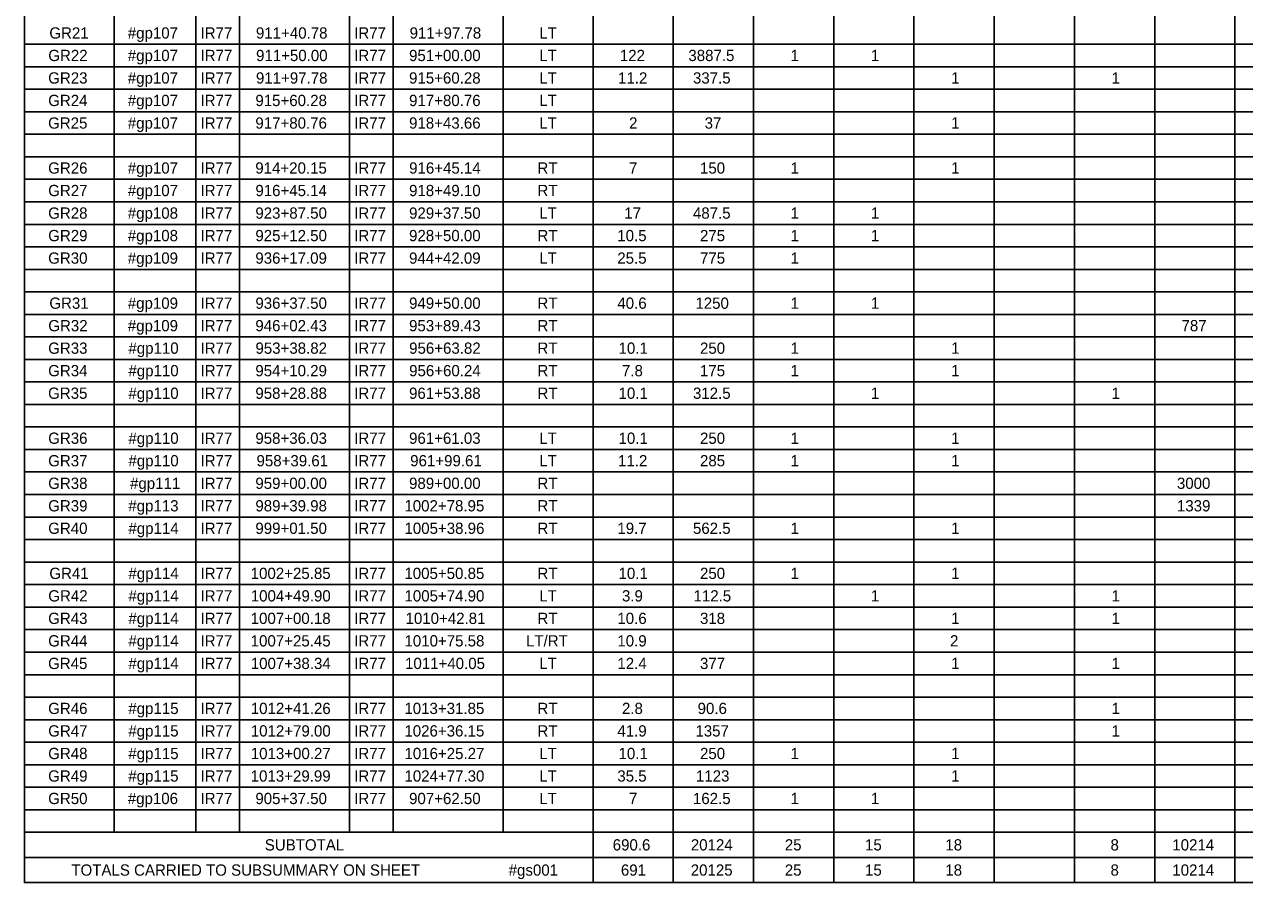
# Model space of a CAD drawing. Extents: x -542 to 295, y -281 to 32.
# Drawn here: x -16.42 to -1.5, y -100.59 to -90.1 of the extents above; entities that cross this region are included whole.
import ezdxf

# ---------------------------------------------------------------- set-up
doc = ezdxf.new("R2010")
doc.units = 0
doc.layers.add('SC_Scratch1', color=7, linetype='Continuous')
doc.layers.add('SH_Text', color=7, linetype='Continuous')

msp = doc.modelspace()

# ---------------------------------------------------------------- linework, layer by layer
at = {"layer": 'SC_Scratch1'}
msp.add_lwpolyline([(-16.421, -79.593), (14.079, -79.593), (14.079, -100.593), (-16.421, -100.593)], close=True, dxfattribs=at)
at = {"layer": 'SH_Text'}
for p, q in [((-16.421, -79.593), (-16.421, -100.593)), ((-15.323, -79.593), (-15.323, -99.977)), ((-14.325, -79.593), (-14.325, -99.977)), ((-10.567, -79.593), (-10.567, -99.977)), ((-9.469, -79.593), (-9.469, -100.593)), ((-8.488, -79.593), (-8.488, -100.593)), ((-7.507, -79.593), (-7.507, -100.593)), ((-6.526, -79.593), (-6.526, -100.593)), ((-5.545, -79.593), (-5.545, -100.593)), ((-4.563, -79.593), (-4.563, -100.593)), ((-3.582, -79.593), (-3.582, -100.593)), ((-2.601, -79.593), (-2.601, -100.593)), ((-1.62, -79.593), (-1.62, -100.593)), ((-12.446, -82.847), (-12.446, -99.977)), ((-13.793, -83.187), (-13.793, -99.977)), ((-11.914, -83.187), (-11.914, -99.977)), ((-16.421, -90.344), (14.079, -90.344)), ((-16.421, -90.619), (14.079, -90.619)), ((-16.421, -90.894), (14.079, -90.894)), ((-16.421, -91.169), (14.079, -91.169)), ((-16.421, -91.445), (14.079, -91.445)), ((-16.421, -91.72), (14.079, -91.72)), ((-16.421, -91.995), (14.079, -91.995)), ((-16.421, -92.27), (14.079, -92.27)), ((-16.421, -92.546), (14.079, -92.546)), ((-16.421, -92.821), (14.079, -92.821)), ((-16.421, -93.096), (14.079, -93.096)), ((-16.421, -93.371), (14.079, -93.371)), ((-16.421, -93.647), (14.079, -93.647)), ((-16.421, -93.922), (14.079, -93.922)), ((-16.421, -94.197), (14.079, -94.197)), ((-16.421, -94.472), (14.079, -94.472)), ((-16.421, -94.748), (14.079, -94.748)), ((-16.421, -95.023), (14.079, -95.023)), ((-16.421, -95.298), (14.079, -95.298)), ((-16.421, -95.573), (14.079, -95.573)), ((-16.421, -95.849), (14.079, -95.849)), ((-16.421, -96.124), (14.079, -96.124)), ((-16.421, -96.399), (14.079, -96.399)), ((-16.421, -96.674), (14.079, -96.674)), ((-16.421, -96.95), (14.079, -96.95)), ((-16.421, -97.225), (14.079, -97.225)), ((-16.421, -97.5), (14.079, -97.5)), ((-16.421, -97.775), (14.079, -97.775)), ((-16.421, -98.051), (14.079, -98.051)), ((-16.421, -98.326), (14.079, -98.326)), ((-16.421, -98.601), (14.079, -98.601)), ((-16.421, -98.876), (14.079, -98.876)), ((-16.421, -99.152), (14.079, -99.152)), ((-16.421, -99.427), (14.079, -99.427)), ((-16.421, -99.702), (14.079, -99.702)), ((-16.421, -99.977), (14.079, -99.977)), ((-16.421, -100.285), (14.079, -100.285)), ((-16.421, -100.593), (14.079, -100.593))]:
    msp.add_line(p, q, dxfattribs=at)

# ---------------------------------------------------------------- texts
for s, height, p in [('GR21', 0.1376, (-16.116, -90.275)), ('#gp107', 0.1376, (-15.157, -90.275)), ('IR77', 0.1376, (-14.268, -90.275)), ('911+40.78', 0.1376, (-13.59, -90.275)), ('IR77', 0.1376, (-12.389, -90.275)), ('911+97.78', 0.1376, (-11.711, -90.275)), ('LT', 0.1376, (-10.126, -90.275)), ('GR22', 0.1376, (-16.129, -90.55)), ('#gp107', 0.1376, (-15.157, -90.55)), ('IR77', 0.1376, (-14.268, -90.55)), ('911+50.00', 0.1376, (-13.589, -90.55)), ('IR77', 0.1376, (-12.389, -90.55)), ('951+00.00', 0.1376, (-11.718, -90.55)), ('LT', 0.1376, (-10.126, -90.55)), ('122', 0.1376, (-9.141, -90.55)), ('3887.5', 0.1376, (-8.303, -90.55)), ('1', 0.138, (-7.053, -90.55)), ('1', 0.138, (-6.072, -90.55)), ('GR23', 0.1376, (-16.13, -90.825)), ('#gp107', 0.1376, (-15.157, -90.825)), ('IR77', 0.1376, (-14.268, -90.825)), ('911+97.78', 0.1376, (-13.59, -90.825)), ('IR77', 0.1376, (-12.389, -90.825)), ('915+60.28', 0.1376, (-11.718, -90.825)), ('LT', 0.1376, (-10.126, -90.825)), ('11.2', 0.1376, (-9.163, -90.825)), ('337.5', 0.1376, (-8.247, -90.825)), ('1', 0.138, (-5.091, -90.825)), ('1', 0.138, (-3.128, -90.825)), ('GR24', 0.1376, (-16.13, -91.1)), ('#gp107', 0.1376, (-15.157, -91.1)), ('IR77', 0.1376, (-14.268, -91.1)), ('915+60.28', 0.1376, (-13.597, -91.1)), ('IR77', 0.1376, (-12.389, -91.1)), ('917+80.76', 0.1376, (-11.718, -91.1)), ('LT', 0.1376, (-10.126, -91.1)), ('GR25', 0.1376, (-16.131, -91.376)), ('#gp107', 0.1376, (-15.157, -91.376)), ('IR77', 0.1376, (-14.268, -91.376)), ('917+80.76', 0.1376, (-13.597, -91.376)), ('IR77', 0.1376, (-12.389, -91.376)), ('918+43.66', 0.1376, (-11.718, -91.376)), ('LT', 0.1376, (-10.126, -91.376)), ('2', 0.138, (-9.028, -91.376)), ('37', 0.1376, (-8.104, -91.376)), ('1', 0.138, (-5.091, -91.376)), ('GR26', 0.1376, (-16.13, -91.926)), ('#gp107', 0.1376, (-15.157, -91.926)), ('IR77', 0.1376, (-14.268, -91.926)), ('914+20.15', 0.1376, (-13.598, -91.926)), ('IR77', 0.1376, (-12.389, -91.926)), ('916+45.14', 0.1376, (-11.717, -91.926)), ('RT', 0.1376, (-10.148, -91.926)), ('7', 0.138, (-9.029, -91.926)), ('150', 0.1376, (-8.161, -91.926)), ('1', 0.138, (-7.053, -91.926)), ('1', 0.138, (-5.091, -91.926)), ('GR27', 0.1376, (-16.13, -92.201)), ('#gp107', 0.1376, (-15.157, -92.201)), ('IR77', 0.1376, (-14.268, -92.201)), ('916+45.14', 0.1376, (-13.597, -92.201)), ('IR77', 0.1376, (-12.389, -92.201)), ('918+49.10', 0.1376, (-11.718, -92.201)), ('RT', 0.1376, (-10.148, -92.201)), ('GR28', 0.1376, (-16.13, -92.477)), ('#gp108', 0.1376, (-15.157, -92.477)), ('IR77', 0.1376, (-14.268, -92.477)), ('923+87.50', 0.1376, (-13.597, -92.477)), ('IR77', 0.1376, (-12.389, -92.477)), ('929+37.50', 0.1376, (-11.718, -92.477)), ('LT', 0.1376, (-10.126, -92.477)), ('17', 0.1376, (-9.086, -92.477)), ('487.5', 0.1376, (-8.247, -92.477)), ('1', 0.138, (-7.053, -92.477)), ('1', 0.138, (-6.072, -92.477)), ('GR29', 0.1376, (-16.13, -92.752)), ('#gp108', 0.1376, (-15.157, -92.752)), ('IR77', 0.1376, (-14.268, -92.752)), ('925+12.50', 0.1376, (-13.597, -92.752)), ('IR77', 0.1376, (-12.389, -92.752)), ('928+50.00', 0.1376, (-11.718, -92.752)), ('RT', 0.1376, (-10.148, -92.752)), ('10.5', 0.1376, (-9.172, -92.752)), ('275', 0.1376, (-8.161, -92.752)), ('1', 0.138, (-7.053, -92.752)), ('1', 0.138, (-6.072, -92.752)), ('GR30', 0.1376, (-16.13, -93.027)), ('#gp109', 0.1376, (-15.157, -93.027)), ('IR77', 0.1376, (-14.268, -93.027)), ('936+17.09', 0.1376, (-13.597, -93.027)), ('IR77', 0.1376, (-12.389, -93.027)), ('944+42.09', 0.1376, (-11.718, -93.027)), ('LT', 0.1376, (-10.126, -93.027)), ('25.5', 0.1376, (-9.172, -93.027)), ('775', 0.1376, (-8.161, -93.027)), ('1', 0.138, (-7.053, -93.027)), ('GR31', 0.1376, (-16.116, -93.578)), ('#gp109', 0.1376, (-15.157, -93.578)), ('IR77', 0.1376, (-14.268, -93.578)), ('936+37.50', 0.1376, (-13.597, -93.578)), ('IR77', 0.1376, (-12.389, -93.578)), ('949+50.00', 0.1376, (-11.718, -93.578)), ('RT', 0.1376, (-10.148, -93.578)), ('40.6', 0.1376, (-9.171, -93.578)), ('1250', 0.1376, (-8.217, -93.578)), ('1', 0.138, (-7.053, -93.578)), ('1', 0.138, (-6.072, -93.578)), ('GR32', 0.1376, (-16.129, -93.853)), ('#gp109', 0.1376, (-15.157, -93.853)), ('IR77', 0.1376, (-14.268, -93.853)), ('946+02.43', 0.1376, (-13.597, -93.853)), ('IR77', 0.1376, (-12.389, -93.853)), ('953+89.43', 0.1376, (-11.718, -93.853)), ('RT', 0.1376, (-10.148, -93.853)), ('787', 0.1376, (-2.274, -93.853)), ('GR33', 0.1376, (-16.13, -94.128)), ('#gp110', 0.1376, (-15.149, -94.128)), ('IR77', 0.1376, (-14.268, -94.128)), ('953+38.82', 0.1376, (-13.596, -94.128)), ('IR77', 0.1376, (-12.389, -94.128)), ('956+63.82', 0.1376, (-11.717, -94.128)), ('RT', 0.1376, (-10.148, -94.128)), ('10.1', 0.1376, (-9.157, -94.128)), ('250', 0.1376, (-8.161, -94.128)), ('1', 0.138, (-7.053, -94.128)), ('1', 0.138, (-5.091, -94.128)), ('GR34', 0.1376, (-16.13, -94.403)), ('#gp110', 0.1376, (-15.149, -94.403)), ('IR77', 0.1376, (-14.268, -94.403)), ('954+10.29', 0.1376, (-13.597, -94.403)), ('IR77', 0.1376, (-12.389, -94.403)), ('956+60.24', 0.1376, (-11.717, -94.403)), ('RT', 0.1376, (-10.148, -94.403)), ('7.8', 0.1376, (-9.115, -94.403)), ('175', 0.1376, (-8.161, -94.403)), ('1', 0.138, (-7.053, -94.403)), ('1', 0.138, (-5.091, -94.403)), ('GR35', 0.1376, (-16.131, -94.679)), ('#gp110', 0.1376, (-15.149, -94.679)), ('IR77', 0.1376, (-14.268, -94.679)), ('958+28.88', 0.1376, (-13.597, -94.679)), ('IR77', 0.1376, (-12.389, -94.679)), ('961+53.88', 0.1376, (-11.718, -94.679)), ('RT', 0.1376, (-10.148, -94.679)), ('10.1', 0.1376, (-9.157, -94.679)), ('312.5', 0.1376, (-8.247, -94.679)), ('1', 0.138, (-6.072, -94.679)), ('1', 0.138, (-3.128, -94.679)), ('GR36', 0.1376, (-16.13, -95.229)), ('#gp110', 0.1376, (-15.149, -95.229)), ('IR77', 0.1376, (-14.268, -95.229)), ('958+36.03', 0.1376, (-13.597, -95.229)), ('IR77', 0.1376, (-12.389, -95.229)), ('961+61.03', 0.1376, (-11.718, -95.229)), ('LT', 0.1376, (-10.126, -95.229)), ('10.1', 0.1376, (-9.157, -95.229)), ('250', 0.1376, (-8.161, -95.229)), ('1', 0.138, (-7.053, -95.229)), ('1', 0.138, (-5.091, -95.229)), ('GR37', 0.1376, (-16.13, -95.504)), ('#gp110', 0.1376, (-15.149, -95.504)), ('IR77', 0.1376, (-14.268, -95.504)), ('958+39.61', 0.1376, (-13.583, -95.504)), ('IR77', 0.1376, (-12.389, -95.504)), ('961+99.61', 0.1376, (-11.704, -95.504)), ('LT', 0.1376, (-10.126, -95.504)), ('11.2', 0.1376, (-9.163, -95.504)), ('285', 0.1376, (-8.161, -95.504)), ('1', 0.138, (-7.053, -95.504)), ('1', 0.138, (-5.091, -95.504)), ('GR38', 0.1376, (-16.13, -95.78)), ('#gp111', 0.1376, (-15.129, -95.78)), ('IR77', 0.1376, (-14.268, -95.78)), ('959+00.00', 0.1376, (-13.597, -95.78)), ('IR77', 0.1376, (-12.389, -95.78)), ('989+00.00', 0.1376, (-11.718, -95.78)), ('RT', 0.1376, (-10.148, -95.78)), ('3000', 0.1376, (-2.33, -95.78)), ('GR39', 0.1376, (-16.13, -96.055)), ('#gp113', 0.1376, (-15.15, -96.055)), ('IR77', 0.1376, (-14.268, -96.055)), ('989+39.98', 0.1376, (-13.597, -96.055)), ('IR77', 0.1376, (-12.389, -96.055)), ('1002+78.95', 0.1376, (-11.775, -96.055)), ('RT', 0.1376, (-10.148, -96.055)), ('1339', 0.1376, (-2.33, -96.055)), ('GR40', 0.1376, (-16.13, -96.33)), ('#gp114', 0.1376, (-15.149, -96.33)), ('IR77', 0.1376, (-14.268, -96.33)), ('999+01.50', 0.1376, (-13.597, -96.33)), ('IR77', 0.1376, (-12.389, -96.33)), ('1005+38.96', 0.1376, (-11.774, -96.33)), ('RT', 0.1376, (-10.148, -96.33)), ('19.7', 0.1376, (-9.171, -96.33)), ('562.5', 0.1376, (-8.247, -96.33)), ('1', 0.138, (-7.053, -96.33)), ('1', 0.138, (-5.091, -96.33)), ('GR41', 0.1376, (-16.116, -96.881)), ('#gp114', 0.1376, (-15.149, -96.881)), ('IR77', 0.1376, (-14.268, -96.881)), ('1002+25.85', 0.1376, (-13.654, -96.881)), ('IR77', 0.1376, (-12.389, -96.881)), ('1005+50.85', 0.1376, (-11.775, -96.881)), ('RT', 0.1376, (-10.148, -96.881)), ('10.1', 0.1376, (-9.157, -96.881)), ('250', 0.1376, (-8.161, -96.881)), ('1', 0.138, (-7.053, -96.881)), ('1', 0.138, (-5.091, -96.881)), ('GR42', 0.1376, (-16.129, -97.156)), ('#gp114', 0.1376, (-15.149, -97.156)), ('IR77', 0.1376, (-14.268, -97.156)), ('1004+49.90', 0.1376, (-13.653, -97.156)), ('IR77', 0.1376, (-12.389, -97.156)), ('1005+74.90', 0.1376, (-11.774, -97.156)), ('LT', 0.1376, (-10.126, -97.156)), ('3.9', 0.1376, (-9.115, -97.156)), ('112.5', 0.1376, (-8.24, -97.156)), ('1', 0.138, (-6.072, -97.156)), ('1', 0.138, (-3.128, -97.156)), ('GR43', 0.1376, (-16.13, -97.431)), ('#gp114', 0.1376, (-15.149, -97.431)), ('IR77', 0.1376, (-14.268, -97.431)), ('1007+00.18', 0.1376, (-13.654, -97.431)), ('IR77', 0.1376, (-12.389, -97.431)), ('1010+42.81', 0.1376, (-11.761, -97.431)), ('RT', 0.1376, (-10.148, -97.431)), ('10.6', 0.1376, (-9.171, -97.431)), ('318', 0.1376, (-8.161, -97.431)), ('1', 0.138, (-5.091, -97.431)), ('1', 0.138, (-3.128, -97.431)), ('LT/RT', 0.1376, (-10.288, -97.706)), ('GR44', 0.1376, (-16.13, -97.706)), ('#gp114', 0.1376, (-15.149, -97.706)), ('IR77', 0.1376, (-14.268, -97.706)), ('1007+25.45', 0.1376, (-13.654, -97.706)), ('IR77', 0.1376, (-12.389, -97.706)), ('1010+75.58', 0.1376, (-11.774, -97.706)), ('10.9', 0.1376, (-9.171, -97.706)), ('2', 0.138, (-5.104, -97.706)), ('GR45', 0.1376, (-16.131, -97.982)), ('#gp114', 0.1376, (-15.149, -97.982)), ('IR77', 0.1376, (-14.268, -97.982)), ('1007+38.34', 0.1376, (-13.653, -97.982)), ('IR77', 0.1376, (-12.389, -97.982)), ('1011+40.05', 0.1376, (-11.767, -97.982)), ('LT', 0.1376, (-10.126, -97.982)), ('12.4', 0.1376, (-9.171, -97.982)), ('377', 0.1376, (-8.161, -97.982)), ('1', 0.138, (-5.091, -97.982)), ('1', 0.138, (-3.128, -97.982)), ('GR46', 0.1376, (-16.13, -98.532)), ('#gp115', 0.1376, (-15.15, -98.532)), ('IR77', 0.1376, (-14.268, -98.532)), ('1012+41.26', 0.1376, (-13.653, -98.532)), ('IR77', 0.1376, (-12.389, -98.532)), ('1013+31.85', 0.1376, (-11.775, -98.532)), ('RT', 0.1376, (-10.148, -98.532)), ('2.8', 0.1376, (-9.115, -98.532)), ('90.6', 0.1376, (-8.19, -98.532)), ('1', 0.138, (-3.128, -98.532)), ('GR47', 0.1376, (-16.13, -98.807)), ('#gp115', 0.1376, (-15.15, -98.807)), ('IR77', 0.1376, (-14.268, -98.807)), ('1012+79.00', 0.1376, (-13.653, -98.807)), ('IR77', 0.1376, (-12.389, -98.807)), ('1026+36.15', 0.1376, (-11.775, -98.807)), ('RT', 0.1376, (-10.148, -98.807)), ('41.9', 0.1376, (-9.171, -98.807)), ('1357', 0.1376, (-8.217, -98.807)), ('1', 0.138, (-3.128, -98.807)), ('GR48', 0.1376, (-16.13, -99.083)), ('#gp115', 0.1376, (-15.15, -99.083)), ('IR77', 0.1376, (-14.268, -99.083)), ('1013+00.27', 0.1376, (-13.653, -99.083)), ('IR77', 0.1376, (-12.389, -99.083)), ('1016+25.27', 0.1376, (-11.774, -99.083)), ('LT', 0.1376, (-10.126, -99.083)), ('10.1', 0.1376, (-9.157, -99.083)), ('250', 0.1376, (-8.161, -99.083)), ('1', 0.138, (-7.053, -99.083)), ('1', 0.138, (-5.091, -99.083)), ('GR49', 0.1376, (-16.13, -99.358)), ('#gp115', 0.1376, (-15.15, -99.358)), ('IR77', 0.1376, (-14.268, -99.358)), ('1013+29.99', 0.1376, (-13.654, -99.358)), ('IR77', 0.1376, (-12.389, -99.358)), ('1024+77.30', 0.1376, (-11.774, -99.358)), ('LT', 0.1376, (-10.126, -99.358)), ('35.5', 0.1376, (-9.172, -99.358)), ('1123', 0.1376, (-8.21, -99.358)), ('1', 0.138, (-5.091, -99.358)), ('GR50', 0.1376, (-16.13, -99.633)), ('#gp106', 0.1376, (-15.157, -99.633)), ('IR77', 0.1376, (-14.268, -99.633)), ('905+37.50', 0.1376, (-13.597, -99.633)), ('IR77', 0.1376, (-12.389, -99.633)), ('907+62.50', 0.1376, (-11.718, -99.633)), ('LT', 0.1376, (-10.126, -99.633)), ('7', 0.138, (-9.029, -99.633)), ('162.5', 0.1376, (-8.247, -99.633)), ('1', 0.138, (-7.053, -99.633)), ('1', 0.138, (-6.072, -99.633)), ('SUBTOTAL', 0.1376, (-13.482, -100.2)), ('690.6', 0.1376, (-9.228, -100.2)), ('20124', 0.1376, (-8.273, -100.2)), ('25', 0.1376, (-7.124, -100.2)), ('15', 0.1376, (-6.143, -100.2)), ('18', 0.1376, (-5.161, -100.2)), ('8', 0.138, (-3.142, -100.2)), ('10214', 0.1376, (-2.386, -100.2)), ('TOTALS CARRIED TO SUBSUMMARY ON SHEET', 0.13763, (-15.847, -100.508)), ('#gs001', 0.1376, (-10.5, -100.508)), ('691', 0.1376, (-9.128, -100.508)), ('20125', 0.1376, (-8.274, -100.508)), ('25', 0.1376, (-7.124, -100.508)), ('15', 0.1376, (-6.143, -100.508)), ('18', 0.1376, (-5.161, -100.508)), ('8', 0.138, (-3.142, -100.508)), ('10214', 0.1376, (-2.386, -100.508))]:
    msp.add_text(s, height=height, dxfattribs=at).set_placement(p)

doc.saveas('drawing.dxf')
